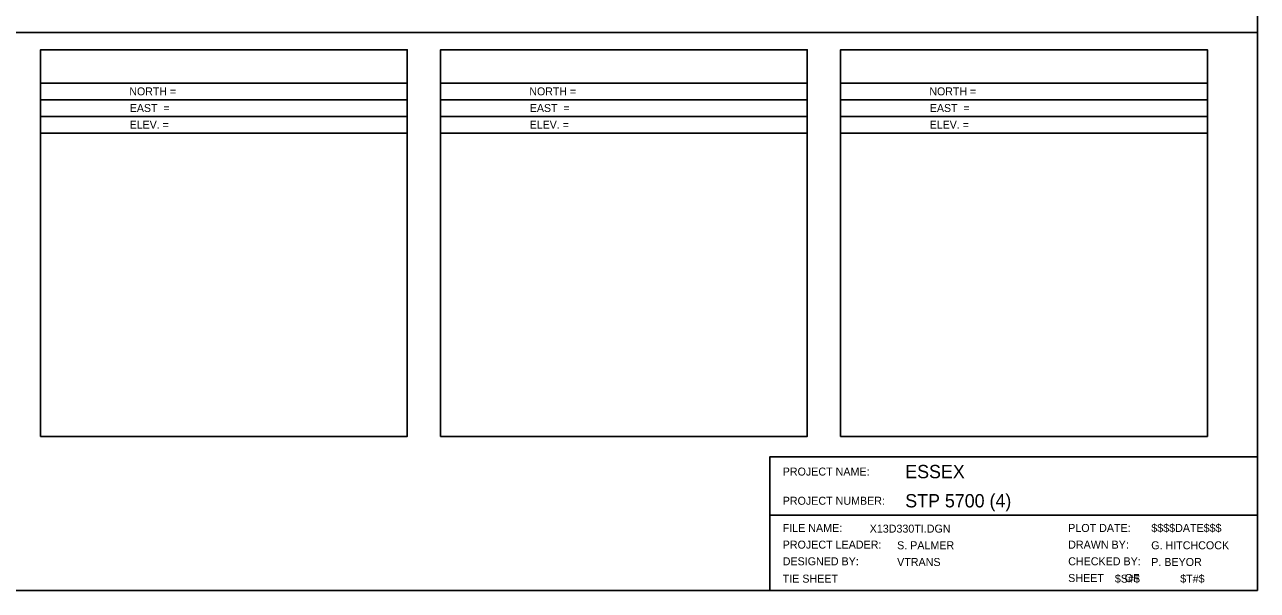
# Model space of a CAD drawing. Extents: x 1478584 to 1479224, y 735365 to 735785.
# Drawn here: x 1478854.7 to 1479224.5, y 735364.5 to 735534.2 of the extents above; entities that cross this region are included whole.
import ezdxf

# ---------------------------------------------------------------- set-up
doc = ezdxf.new("R2010")
doc.units = 0
doc.layers.add('NBL1', color=7, linetype='Continuous')
doc.layers.add('NBL2', color=7, linetype='Continuous')

msp = doc.modelspace()

# ---------------------------------------------------------------- linework, layer by layer
at = {"layer": 'NBL1'}
msp.add_line((1479078.21, 735387.02), (1479224.46, 735387.02), dxfattribs=at)
msp.add_lwpolyline([(1478584.46, 735364.52), (1479224.46, 735364.52), (1479224.46, 735784.52), (1478584.46, 735784.52)], close=True, dxfattribs=at)
msp.add_lwpolyline([(1479224.46, 735404.52), (1479078.21, 735404.52), (1479078.21, 735364.52)], dxfattribs=at)
at = {"layer": 'NBL2'}
for p, q in [((1478584.46, 735531.85), (1479224.46, 735531.85)), ((1478969.46, 735516.68), (1478859.46, 735516.68)), ((1479089.46, 735516.68), (1478979.46, 735516.68)), ((1479209.46, 735516.68), (1479099.46, 735516.68)), ((1478969.46, 735511.68), (1478859.46, 735511.68)), ((1479089.46, 735511.68), (1478979.46, 735511.68)), ((1479209.46, 735511.68), (1479099.46, 735511.68)), ((1478969.46, 735506.68), (1478859.46, 735506.68)), ((1479089.46, 735506.68), (1478979.46, 735506.68)), ((1479209.46, 735506.68), (1479099.46, 735506.68)), ((1478969.46, 735501.68), (1478859.46, 735501.68)), ((1479089.46, 735501.68), (1478979.46, 735501.68)), ((1479209.46, 735501.68), (1479099.46, 735501.68))]:
    msp.add_line(p, q, dxfattribs=at)
for points in [[(1478859.46, 735410.68), (1478969.46, 735410.68), (1478969.46, 735526.68), (1478859.46, 735526.68)], [(1478979.46, 735410.68), (1479089.46, 735410.68), (1479089.46, 735526.68), (1478979.46, 735526.68)], [(1479099.46, 735410.68), (1479209.46, 735410.68), (1479209.46, 735526.68), (1479099.46, 735526.68)]]:
    msp.add_lwpolyline(points, close=True, dxfattribs=at)

# ---------------------------------------------------------------- texts
at = {"layer": 'NBL1'}
for s, height, p in [('PROJECT NAME:', 2.4, (1479082.08, 735398.94)), ('ESSEX                     ', 4, (1479118.84, 735398.14)), ('PROJECT NUMBER:', 2.4, (1479082.08, 735390.19)), ('STP 5700 (4)              ', 4, (1479118.84, 735389.39)), ('FILE NAME:', 2.4, (1479082.08, 735382.03)), ('     X13D330TI.DGN        ', 2.4, (1479103.71, 735381.83)), ('PLOT DATE:', 2.4, (1479167.72, 735382.03)), ('$$$$DATE$$$', 2.4, (1479192.65, 735382.03)), ('PROJECT LEADER:', 2.4, (1479082.08, 735377.03)), ('S. PALMER           ', 2.4, (1479116.4, 735376.83)), ('DRAWN BY:', 2.4, (1479167.72, 735377.03)), ('G. HITCHCOCK ', 2.4, (1479192.63, 735376.83)), ('DESIGNED BY:', 2.4, (1479082.08, 735372.03)), ('VTRANS              ', 2.4, (1479116.4, 735371.83)), ('CHECKED BY:', 2.4, (1479167.72, 735372.03)), ('P. BEYOR     ', 2.4, (1479192.63, 735371.83)), ('TIE SHEET                         ', 2.4, (1479082.08, 735366.83)), ('SHEET       OF', 2.4, (1479167.72, 735367.03)), ('$S#$ ', 2.4, (1479181.71, 735366.83)), ('$T#$   ', 2.4, (1479201.33, 735366.83))]:
    msp.add_text(s, height=height, dxfattribs=at).set_placement(p)
at = {"layer": 'NBL2'}
for s, p in [('NORTH =             ', (1478886.08, 735513)), ('NORTH =             ', (1479006.08, 735513)), ('NORTH =             ', (1479126.08, 735513)), ('EAST  =             ', (1478886.22, 735508)), ('EAST  =             ', (1479006.22, 735508)), ('EAST  =             ', (1479126.22, 735508)), ('ELEV. =             ', (1478886.18, 735503)), ('ELEV. =             ', (1479006.18, 735503)), ('ELEV. =             ', (1479126.18, 735503))]:
    msp.add_text(s, height=2.375, dxfattribs=at).set_placement(p)

doc.saveas('drawing.dxf')
